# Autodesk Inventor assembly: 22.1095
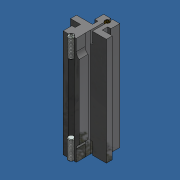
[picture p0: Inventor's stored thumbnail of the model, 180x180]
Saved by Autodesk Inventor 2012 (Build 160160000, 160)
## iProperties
Created: 2007-06
Part Number: 22.1095
Document SubType Name: Assembly
Designer: Andy Moles
Description: SLIDE RAIL LN
Vendor: S
Mass: 40.1475 g
Surface Area: 149.209 cm^2
Volume: 37.325 cm^3
Density: 1.07562 g/cm^3
Author: Andy Moles
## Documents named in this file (4)
- C:\Andys Backup Data\ANDY'S INVENTOR\INVENTOR LIBRARIES\PARTS LIBRARY\COMPONENTS LG\22.1095 SLIDE RAIL LN.iam
- C:\Andys Backup Data\ANDY'S INVENTOR\INVENTOR LIBRARIES\PARTS LIBRARY\COMPONENTS LG\SUBCOMPONENTS\22.1095_1 SLIDE RAIL LN.ipt
- C:\Andys Backup Data\ANDY'S INVENTOR\INVENTOR LIBRARIES\PARTS LIBRARY\FASTENING ELEMENTS\SET SCREWS\21.1314 M4x8 SET SCREW POINTED.IPT
- C:\Andys Backup Data\ANDY'S INVENTOR\INVENTOR LIBRARIES\PARTS LIBRARY\FASTENING ELEMENTS\SET SCREWS\21.1302 M5X16 SET SCREW FLAT.ipt
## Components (5 placed, 3 different names)
1. 22.1095_1 SLIDE RAIL LN:1 — Insert:1, Insert:2, Flush:1, Flush:2, Mate:1, Mate:2
2. 21.1314 M4X8 SET SCREW CONE POINT DIN 914:1 — Insert:1
3. 21.1314 M4X8 SET SCREW CONE POINT DIN 914:2 — Insert:2
4. 21.1302 M5x16 Set Screw Flat Point DIN 913:1 — Flush:2, Mate:1, Mate:3
5. 21.1302 M5x16 Set Screw Flat Point DIN 913:2 — Flush:1, Mate:2, Mate:3
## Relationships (7: Mate 3, Insert 2, Flush 2)
- Insert:1: 22.1095_1 SLIDE RAIL LN:1 ↔ 21.1314 M4X8 SET SCREW CONE POINT DIN 914:1
- Insert:2: 22.1095_1 SLIDE RAIL LN:1 ↔ 21.1314 M4X8 SET SCREW CONE POINT DIN 914:2
- Flush:1: 22.1095_1 SLIDE RAIL LN:1 ↔ 21.1302 M5x16 Set Screw Flat Point DIN 913:2
- Flush:2: 22.1095_1 SLIDE RAIL LN:1 ↔ 21.1302 M5x16 Set Screw Flat Point DIN 913:1
- Mate:1: 22.1095_1 SLIDE RAIL LN:1 ↔ 21.1302 M5x16 Set Screw Flat Point DIN 913:1
- Mate:2: 22.1095_1 SLIDE RAIL LN:1 ↔ 21.1302 M5x16 Set Screw Flat Point DIN 913:2
- Mate:3: 21.1302 M5x16 Set Screw Flat Point DIN 913:1 ↔ 21.1302 M5x16 Set Screw Flat Point DIN 913:2
